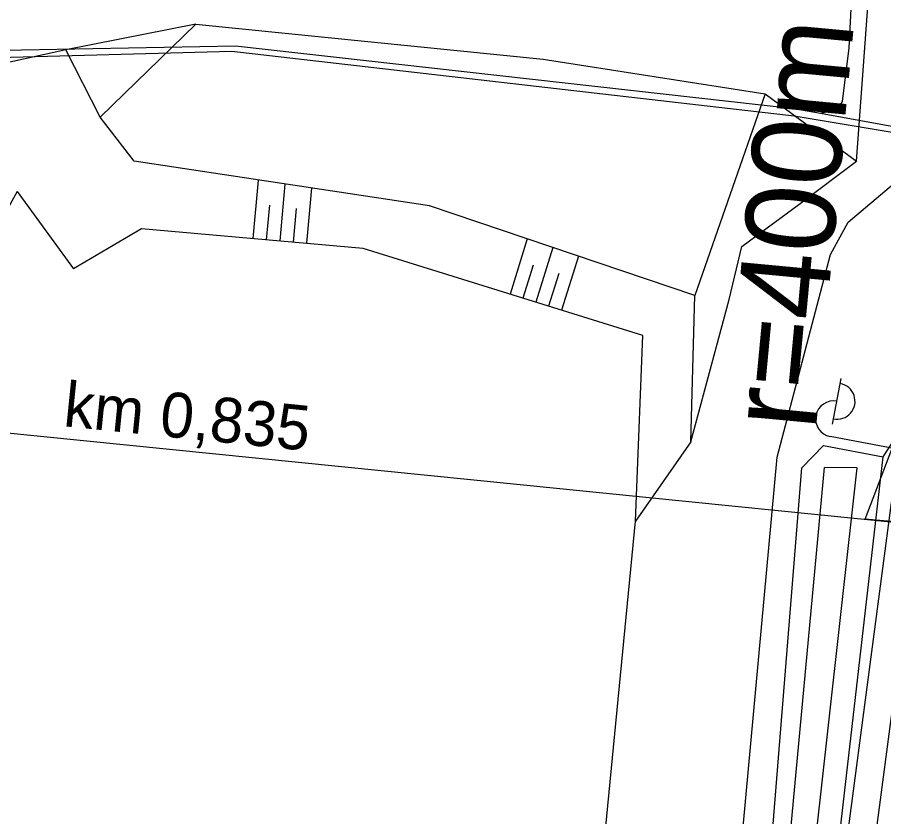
# Model space of a CAD drawing. Extents: x -598638 to -597933, y -1164002 to -1161904.
# Drawn here: x -598309.45 to -598261.16, y -1163238.11 to -1163193.56 of the extents above; entities that cross this region are included whole.
import ezdxf

# ---------------------------------------------------------------- set-up
doc = ezdxf.new("R2010")
doc.units = 0
for name, color, linetype in [('Vrstva 1', 7, 'Continuous'), ('Vrstva 25', 7, 'Continuous'), ('Vrstva 26', 7, 'Continuous'), ('Vrstva 28', 7, 'Continuous'), ('Vrstva 31', 7, 'Continuous'), ('Vrstva 4', 7, 'Continuous'), ('Vrstva 48', 7, 'Continuous'), ('Vrstva 49', 7, 'Continuous'), ('Vrstva 51', 7, 'Continuous')]:
    doc.layers.add(name, color=color, linetype=linetype)

msp = doc.modelspace()

# ---------------------------------------------------------------- linework, layer by layer
at = {"layer": 'Vrstva 1'}
msp.add_line((-598333.891, -1163214.308), (-598257.805, -1163221.972), dxfattribs=at)
at = {"layer": 'Vrstva 25'}
for p, q in [((-598264.013, -1163216.233), (-598263.524, -1163213.679)), ((-598260.707, -1163217.579), (-598264.145, -1163216.92))]:
    msp.add_line(p, q, dxfattribs=at)
for centre, start, end in [((-598263.756, -1163214.958), 258.4533, 79.8585), ((-598263.956, -1163215.938), 79.1559, 259.1559)]:
    msp.add_arc(centre, 1, start, end, dxfattribs=at)
at = {"layer": 'Vrstva 26'}
for points in [[(-598264.673, -1163198.892), (-598263.736, -1163198.689), (-598263.455, -1163198.252), (-598263.08, -1163195.259), (-598262.88, -1163191.25), (-598263.188, -1163181.396), (-598262.757, -1163172.789), (-598262.593, -1163169.932), (-598262.804, -1163168.342), (-598266.75, -1163166.686), (-598267.463, -1163166.395), (-598268.132, -1163166.799), (-598268.224, -1163167.621)], [(-598329.728, -1163196.743), (-598327.762, -1163195.73), (-598319.884, -1163195.578), (-598311.212, -1163195.415), (-598297.281, -1163195.142), (-598266.17, -1163198.65), (-598264.673, -1163198.892)], [(-598264.673, -1163198.892), (-598259.279, -1163199.882), (-598251.555, -1163200.359)], [(-598252.716, -1163222.377), (-598262.19, -1163221.532), (-598260.699, -1163217.627), (-598260.216, -1163217.673)]]:
    msp.add_lwpolyline(points, dxfattribs=at)
at = {"layer": 'Vrstva 28'}
msp.add_lwpolyline([(-598360.628, -1163250.687), (-598347.056, -1163227.008), (-598343.69, -1163221.941), (-598334.357, -1163205.599), (-598329.437, -1163196.714), (-598327.818, -1163196), (-598319.941, -1163195.997), (-598311.197, -1163195.818), (-598297.498, -1163195.446), (-598266.143, -1163199.05), (-598259.229, -1163200.197), (-598251.389, -1163200.707), (-598251.78, -1163201.97), (-598251.81, -1163204.88), (-598252.12, -1163206.93), (-598252.19, -1163209.91), (-598252.91, -1163219.87), (-598253.43, -1163232.8), (-598254.31, -1163244.16)], dxfattribs=at)
at = {"layer": 'Vrstva 31'}
msp.add_lwpolyline([(-598445.119, -1163438.183), (-598442.838, -1163432.572), (-598442.56, -1163432.17), (-598442.26, -1163430.07), (-598433.21, -1163395.711), (-598423.503, -1163370.002), (-598418.049, -1163355.705), (-598405.678, -1163328.228), (-598398.251, -1163314.957), (-598386.091, -1163294.234), (-598371.931, -1163269.732), (-598360.628, -1163250.687), (-598347.056, -1163227.008), (-598343.69, -1163221.941), (-598334.357, -1163205.599), (-598329.437, -1163196.714), (-598327.818, -1163196), (-598319.941, -1163195.997), (-598311.197, -1163195.818), (-598297.498, -1163195.446), (-598266.143, -1163199.05), (-598259.229, -1163200.197), (-598251.389, -1163200.707), (-598251.058, -1163204.207)], dxfattribs=at)
at = {"layer": 'Vrstva 4'}
msp.add_lwpolyline([(-598398.167, -1163553.239), (-598376.487, -1163515.918), (-598348.795, -1163467.979), (-598339.716, -1163452.202), (-598323.266, -1163423.236), (-598308.372, -1163396.471), (-598302.715, -1163384.123), (-598298.324, -1163372.137), (-598289.593, -1163344.221), (-598282.967, -1163321.229), (-598274.797, -1163290.285), (-598269.404, -1163272.781), (-598266.519, -1163258.633), (-598263.896, -1163241.651), (-598261.185, -1163218.05), (-598260.503, -1163217.001), (-598259.092, -1163201.513), (-598258.163, -1163186.176), (-598256.557, -1163141.317), (-598256.485, -1163129.008), (-598255.651, -1163108.451), (-598254.34, -1163087.718), (-598253.319, -1163075.132)], dxfattribs=at)
at = {"layer": 'Vrstva 48'}
for p, q in [((-598296.027, -1163202.628), (-598296.316, -1163205.888)), ((-598294.541, -1163202.853), (-598294.822, -1163206.021)), ((-598293.056, -1163203.077), (-598293.329, -1163206.153)), ((-598295.398, -1163204.026), (-598295.569, -1163205.955)), ((-598293.909, -1163204.214), (-598294.076, -1163206.087)), ((-598281.021, -1163205.909), (-598281.983, -1163208.989)), ((-598279.6, -1163206.388), (-598280.552, -1163209.436)), ((-598278.178, -1163206.867), (-598279.12, -1163209.884)), ((-598280.693, -1163207.374), (-598281.268, -1163209.213)), ((-598279.268, -1163207.841), (-598279.836, -1163209.66))]:
    msp.add_line(p, q, dxfattribs=at)
at = {"layer": 'Vrstva 49'}
for p, q in [((-598299.488, -1163193.95), (-598306.738, -1163195.378)), ((-598267.761, -1163197.821), (-598271.685, -1163209.056)), ((-598267.761, -1163197.821), (-598262.679, -1163201.583)), ((-598271.914, -1163217.222), (-598274.987, -1163221.639))]:
    msp.add_line(p, q, dxfattribs=at)
for points in [[(-598299.445, -1163361.058), (-598297.068, -1163359.059), (-598293.068, -1163343.621), (-598287.79, -1163320.649), (-598279.637, -1163288.312), (-598274.636, -1163271.434), (-598271.523, -1163257.595), (-598269.283, -1163241.904), (-598267.104, -1163218.072), (-598264.127, -1163206.783), (-598263.144, -1163204.971), (-598260.62, -1163202.843), (-598259.578, -1163186.018), (-598258.253, -1163141.176), (-598259.192, -1163127.718), (-598260.075, -1163119.279), (-598261.182, -1163115.692), (-598261.349, -1163113.122), (-598258.894, -1163101.538), (-598255.65, -1163087.809), (-598254.518, -1163075.132), (-598252.098, -1163061.479), (-598247.841, -1163044.835)], [(-598271.914, -1163217.222), (-598269.776, -1163209.288), (-598269.073, -1163206.337), (-598265.809, -1163203.939), (-598262.679, -1163201.583), (-598261.749, -1163188.913), (-598261.649, -1163166.383), (-598262.017, -1163142.76), (-598263.36, -1163128.202), (-598263.105, -1163118.751), (-598268.545, -1163115.616), (-598275.334, -1163113.816), (-598312.096, -1163191.704), (-598312.746, -1163196.691)], [(-598304.823, -1163199.126), (-598299.488, -1163193.95), (-598280.132, -1163195.887), (-598267.761, -1163197.821)], [(-598271.914, -1163217.222), (-598271.685, -1163209.056), (-598286.468, -1163204.073), (-598302.929, -1163201.585), (-598304.823, -1163199.126), (-598306.738, -1163195.378), (-598312.746, -1163196.691)], [(-598309.446, -1163203.262), (-598316.229, -1163215.539), (-598313.873, -1163217.741), (-598321.933, -1163233.799), (-598326.308, -1163254.29), (-598324.871, -1163281.374), (-598324.668, -1163290.005), (-598320.258, -1163307.426), (-598325.507, -1163312.636), (-598323.584, -1163327.934), (-598325.353, -1163339.082), (-598298.967, -1163343.623), (-598293.544, -1163316.86), (-598287.625, -1163290.34), (-598280.443, -1163265.616), (-598276.989, -1163242.095), (-598274.987, -1163221.639), (-598274.592, -1163211.298), (-598290.163, -1163206.434), (-598302.523, -1163205.338), (-598306.323, -1163207.572)], [(-598309.446, -1163203.262), (-598306.323, -1163207.572)], [(-598350.075, -1163469.161), (-598350.962, -1163468.642), (-598341.128, -1163451.449), (-598324.91, -1163422.41), (-598309.936, -1163395.461), (-598304.358, -1163383.215), (-598300.139, -1163371.399), (-598292.224, -1163343.911), (-598285.916, -1163320.98), (-598277.492, -1163289.124), (-598272.642, -1163272.084), (-598269.771, -1163257.778), (-598267.544, -1163241.285), (-598265.728, -1163218.657), (-598264.511, -1163217.412), (-598261.185, -1163218.05)], [(-598350.962, -1163468.642), (-598340.803, -1163451.583), (-598324.406, -1163422.648), (-598309.58, -1163395.796), (-598303.887, -1163383.446), (-598299.666, -1163371.582), (-598291.401, -1163343.859), (-598285.02, -1163321.209), (-598276.751, -1163289.495), (-598271.739, -1163271.843), (-598268.729, -1163258.218), (-598266.553, -1163241.22), (-598264.463, -1163218.64)], [(-598350.075, -1163469.161), (-598340.252, -1163451.87), (-598323.84, -1163422.849), (-598308.915, -1163396.15), (-598303.181, -1163383.749), (-598299.003, -1163371.924), (-598290.374, -1163343.997), (-598283.872, -1163321.586), (-598275.648, -1163289.867), (-598270.185, -1163272.379), (-598267.391, -1163258.396), (-598265.172, -1163241.341), (-598262.635, -1163218.663), (-598264.463, -1163218.64)]]:
    msp.add_lwpolyline(points, dxfattribs=at)
at = {"layer": 'Vrstva 51'}
for points in [[(-598397.431, -1163553.318), (-598375.745, -1163515.943), (-598348.098, -1163468.333), (-598322.38, -1163423.533), (-598307.542, -1163396.818), (-598301.86, -1163384.541), (-598297.285, -1163372.341), (-598293.283, -1163359.379), (-598288.845, -1163344.448), (-598282.25, -1163321.235), (-598273.825, -1163290.423), (-598265.756, -1163258.778), (-598260.545, -1163219.203), (-598259.744, -1163217.171), (-598258.57, -1163201.891), (-598257.659, -1163186.255), (-598256.038, -1163142.193), (-598255.793, -1163128.623), (-598255.065, -1163108.27), (-598253.781, -1163088.998), (-598252.62, -1163075.466)], [(-598396.078, -1163554.151), (-598374.443, -1163516.599), (-598347.031, -1163469.014), (-598321.218, -1163424.261), (-598306.253, -1163397.723), (-598300.608, -1163385.153), (-598295.814, -1163372.93), (-598291.849, -1163359.988), (-598287.46, -1163344.41), (-598281.154, -1163322.32), (-598272.412, -1163291.197), (-598264.229, -1163259.135), (-598258.972, -1163219.27), (-598257.327, -1163201.644), (-598256.369, -1163186.491), (-598254.79, -1163142.649), (-598254.397, -1163128.629), (-598253.571, -1163108.317), (-598252.585, -1163090.153), (-598250.983, -1163076.012)]]:
    msp.add_lwpolyline(points, dxfattribs=at)

# ---------------------------------------------------------------- texts
at = {"layer": 'Vrstva 1'}
for s, height, rotation, p in [('r=400m', 5, 84.6357, (-598264.947, -1163216.647)), ('km 0,835', 2.5, 354.2439, (-598306.933, -1163216.343))]:
    msp.add_text(s, height=height, rotation=rotation, dxfattribs=at).set_placement(p)

doc.saveas('drawing.dxf')
